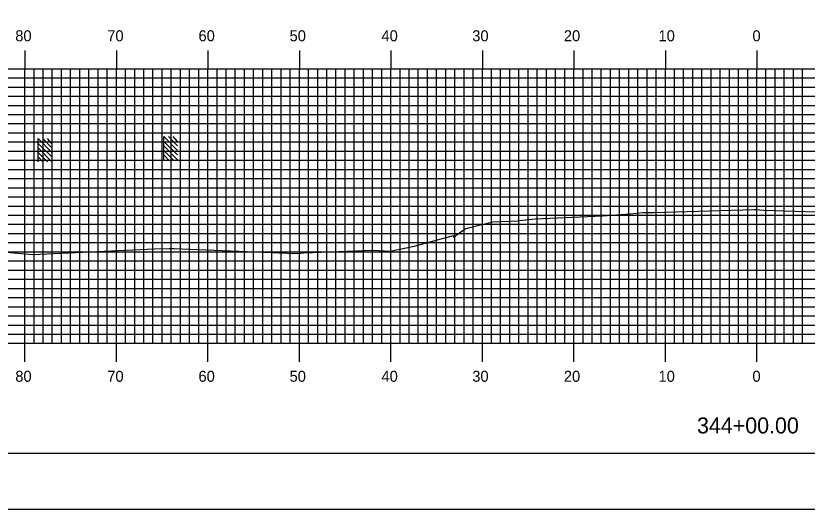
# Model space of a CAD drawing. Extents: x 1825540 to 1825883, y 442591 to 442811.
# Drawn here: x 1825624.9 to 1825711.4, y 442590.5 to 442644.4 of the extents above; entities that cross this region are included whole.
import ezdxf

# ---------------------------------------------------------------- set-up
doc = ezdxf.new("R2010")
doc.units = 0
for name, color, linetype in [('BORDER', 7, 'Continuous'), ('H_V ANNOTATION', 7, 'Continuous'), ('M_Buildings_Rooftop', 7, 'Continuous'), ('MAJOR', 7, 'Continuous'), ('MINOR', 7, 'Continuous'), ('PLOT BOUNDARY', 7, 'Continuous'), ('S_Roadway_Centerline', 7, 'Continuous')]:
    doc.layers.add(name, color=color, linetype=linetype)

msp = doc.modelspace()

# ---------------------------------------------------------------- linework, layer by layer
at = {"layer": 'BORDER'}
msp.add_lwpolyline([(1825556.274, 442596.665), (1825876.274, 442596.665), (1825876.274, 442806.665), (1825556.274, 442806.665)], close=True, dxfattribs=at)
at = {"layer": 'M_Buildings_Rooftop'}
for p, q in [((1825641.046, 442628.725), (1825641.046, 442631.251)), ((1825642.555, 442629.742), (1825641.046, 442631.251)), ((1825642.555, 442630.234), (1825641.571, 442631.251)), ((1825642.555, 442630.726), (1825642.063, 442631.251)), ((1825627.311, 442628.501), (1825627.311, 442631.027)), ((1825628.821, 442629.518), (1825627.311, 442631.027)), ((1825628.821, 442629.026), (1825627.311, 442630.502)), ((1825628.821, 442630.01), (1825627.836, 442631.027)), ((1825628.821, 442630.502), (1825628.328, 442631.027)), ((1825642.555, 442629.25), (1825641.046, 442630.726)), ((1825642.555, 442628.725), (1825641.046, 442630.234)), ((1825628.821, 442628.501), (1825627.311, 442630.01)), ((1825628.328, 442628.501), (1825627.311, 442629.518)), ((1825642.063, 442628.725), (1825641.046, 442629.742)), ((1825627.836, 442628.501), (1825627.311, 442629.026)), ((1825641.571, 442628.725), (1825641.046, 442629.25))]:
    msp.add_line(p, q, dxfattribs=at)
at = {"layer": 'MAJOR'}
for p, q in [((1825625.874, 442640.669), (1825625.874, 442638.665)), ((1825635.874, 442640.669), (1825635.874, 442638.665)), ((1825645.874, 442640.669), (1825645.874, 442638.665)), ((1825655.874, 442640.669), (1825655.874, 442638.665)), ((1825665.874, 442640.669), (1825665.874, 442638.665)), ((1825675.874, 442640.669), (1825675.874, 442638.665)), ((1825685.874, 442640.669), (1825685.874, 442638.665)), ((1825695.874, 442640.669), (1825695.874, 442638.665)), ((1825705.874, 442640.669), (1825705.874, 442638.665)), ((1825565.874, 442638.665), (1825845.874, 442638.665)), ((1825565.874, 442638.665), (1825845.874, 442638.665)), ((1825625.874, 442608.665), (1825625.874, 442638.665)), ((1825635.874, 442608.665), (1825635.874, 442638.665)), ((1825645.874, 442608.665), (1825645.874, 442638.665)), ((1825655.874, 442608.665), (1825655.874, 442638.665)), ((1825665.874, 442608.665), (1825665.874, 442638.665)), ((1825675.874, 442608.665), (1825675.874, 442638.665)), ((1825685.874, 442608.665), (1825685.874, 442638.665)), ((1825695.874, 442608.665), (1825695.874, 442638.665)), ((1825705.874, 442608.665), (1825705.874, 442638.665)), ((1825565.874, 442633.665), (1825845.874, 442633.665)), ((1825565.874, 442628.665), (1825845.874, 442628.665)), ((1825565.874, 442623.665), (1825845.874, 442623.665)), ((1825565.874, 442618.665), (1825845.874, 442618.665)), ((1825565.874, 442613.665), (1825845.874, 442613.665)), ((1825565.874, 442608.665), (1825845.874, 442608.665)), ((1825565.874, 442608.665), (1825845.874, 442608.665)), ((1825625.874, 442606.661), (1825625.874, 442608.665)), ((1825635.874, 442606.661), (1825635.874, 442608.665)), ((1825645.874, 442606.661), (1825645.874, 442608.665)), ((1825655.874, 442606.661), (1825655.874, 442608.665)), ((1825665.874, 442606.661), (1825665.874, 442608.665)), ((1825675.874, 442606.661), (1825675.874, 442608.665)), ((1825685.874, 442606.661), (1825685.874, 442608.665)), ((1825695.874, 442606.661), (1825695.874, 442608.665)), ((1825705.874, 442606.661), (1825705.874, 442608.665))]:
    msp.add_line(p, q, dxfattribs=at)
at = {"layer": 'MINOR'}
for p, q in [((1825626.874, 442608.665), (1825626.874, 442638.665)), ((1825627.874, 442608.665), (1825627.874, 442638.665)), ((1825628.874, 442608.665), (1825628.874, 442638.665)), ((1825629.874, 442608.665), (1825629.874, 442638.665)), ((1825630.874, 442608.665), (1825630.874, 442638.665)), ((1825631.874, 442608.665), (1825631.874, 442638.665)), ((1825632.874, 442608.665), (1825632.874, 442638.665)), ((1825633.874, 442608.665), (1825633.874, 442638.665)), ((1825634.874, 442608.665), (1825634.874, 442638.665)), ((1825636.874, 442608.665), (1825636.874, 442638.665)), ((1825637.874, 442608.665), (1825637.874, 442638.665)), ((1825638.874, 442608.665), (1825638.874, 442638.665)), ((1825639.874, 442608.665), (1825639.874, 442638.665)), ((1825640.874, 442608.665), (1825640.874, 442638.665)), ((1825641.874, 442608.665), (1825641.874, 442638.665)), ((1825642.874, 442608.665), (1825642.874, 442638.665)), ((1825643.874, 442608.665), (1825643.874, 442638.665)), ((1825644.874, 442608.665), (1825644.874, 442638.665)), ((1825646.874, 442608.665), (1825646.874, 442638.665)), ((1825647.874, 442608.665), (1825647.874, 442638.665)), ((1825648.874, 442608.665), (1825648.874, 442638.665)), ((1825649.874, 442608.665), (1825649.874, 442638.665)), ((1825650.874, 442608.665), (1825650.874, 442638.665)), ((1825651.874, 442608.665), (1825651.874, 442638.665)), ((1825652.874, 442608.665), (1825652.874, 442638.665)), ((1825653.874, 442608.665), (1825653.874, 442638.665)), ((1825654.874, 442608.665), (1825654.874, 442638.665)), ((1825656.874, 442608.665), (1825656.874, 442638.665)), ((1825657.874, 442608.665), (1825657.874, 442638.665)), ((1825658.874, 442608.665), (1825658.874, 442638.665)), ((1825659.874, 442608.665), (1825659.874, 442638.665)), ((1825660.874, 442608.665), (1825660.874, 442638.665)), ((1825661.874, 442608.665), (1825661.874, 442638.665)), ((1825662.874, 442608.665), (1825662.874, 442638.665)), ((1825663.874, 442608.665), (1825663.874, 442638.665)), ((1825664.874, 442608.665), (1825664.874, 442638.665)), ((1825666.874, 442608.665), (1825666.874, 442638.665)), ((1825667.874, 442608.665), (1825667.874, 442638.665)), ((1825668.874, 442608.665), (1825668.874, 442638.665)), ((1825669.874, 442608.665), (1825669.874, 442638.665)), ((1825670.874, 442608.665), (1825670.874, 442638.665)), ((1825671.874, 442608.665), (1825671.874, 442638.665)), ((1825672.874, 442608.665), (1825672.874, 442638.665)), ((1825673.874, 442608.665), (1825673.874, 442638.665)), ((1825674.874, 442608.665), (1825674.874, 442638.665)), ((1825676.874, 442608.665), (1825676.874, 442638.665)), ((1825677.874, 442608.665), (1825677.874, 442638.665)), ((1825678.874, 442608.665), (1825678.874, 442638.665)), ((1825679.874, 442608.665), (1825679.874, 442638.665)), ((1825680.874, 442608.665), (1825680.874, 442638.665)), ((1825681.874, 442608.665), (1825681.874, 442638.665)), ((1825682.874, 442608.665), (1825682.874, 442638.665)), ((1825683.874, 442608.665), (1825683.874, 442638.665)), ((1825684.874, 442608.665), (1825684.874, 442638.665)), ((1825686.874, 442608.665), (1825686.874, 442638.665)), ((1825687.874, 442608.665), (1825687.874, 442638.665)), ((1825688.874, 442608.665), (1825688.874, 442638.665)), ((1825689.874, 442608.665), (1825689.874, 442638.665)), ((1825690.874, 442608.665), (1825690.874, 442638.665)), ((1825691.874, 442608.665), (1825691.874, 442638.665)), ((1825692.874, 442608.665), (1825692.874, 442638.665)), ((1825693.874, 442608.665), (1825693.874, 442638.665)), ((1825694.874, 442608.665), (1825694.874, 442638.665)), ((1825696.874, 442608.665), (1825696.874, 442638.665)), ((1825697.874, 442608.665), (1825697.874, 442638.665)), ((1825698.874, 442608.665), (1825698.874, 442638.665)), ((1825699.874, 442608.665), (1825699.874, 442638.665)), ((1825700.874, 442608.665), (1825700.874, 442638.665)), ((1825701.874, 442608.665), (1825701.874, 442638.665)), ((1825702.874, 442608.665), (1825702.874, 442638.665)), ((1825703.874, 442608.665), (1825703.874, 442638.665)), ((1825704.874, 442608.665), (1825704.874, 442638.665)), ((1825706.874, 442608.665), (1825706.874, 442638.665)), ((1825707.874, 442608.665), (1825707.874, 442638.665)), ((1825708.874, 442608.665), (1825708.874, 442638.665)), ((1825709.874, 442608.665), (1825709.874, 442638.665)), ((1825710.874, 442608.665), (1825710.874, 442638.665)), ((1825565.874, 442637.665), (1825845.874, 442637.665)), ((1825565.874, 442636.665), (1825845.874, 442636.665)), ((1825565.874, 442635.665), (1825845.874, 442635.665)), ((1825565.874, 442634.665), (1825845.874, 442634.665)), ((1825565.874, 442632.665), (1825845.874, 442632.665)), ((1825565.874, 442631.665), (1825845.874, 442631.665)), ((1825565.874, 442630.665), (1825845.874, 442630.665)), ((1825565.874, 442629.665), (1825845.874, 442629.665)), ((1825565.874, 442627.665), (1825845.874, 442627.665)), ((1825565.874, 442626.665), (1825845.874, 442626.665)), ((1825565.874, 442625.665), (1825845.874, 442625.665)), ((1825565.874, 442624.665), (1825845.874, 442624.665)), ((1825565.874, 442622.665), (1825845.874, 442622.665)), ((1825565.874, 442621.665), (1825845.874, 442621.665)), ((1825565.874, 442620.665), (1825845.874, 442620.665)), ((1825565.874, 442619.665), (1825845.874, 442619.665)), ((1825565.874, 442617.665), (1825845.874, 442617.665)), ((1825565.874, 442616.665), (1825845.874, 442616.665)), ((1825565.874, 442615.665), (1825845.874, 442615.665)), ((1825565.874, 442614.665), (1825845.874, 442614.665)), ((1825565.874, 442612.665), (1825845.874, 442612.665)), ((1825565.874, 442611.665), (1825845.874, 442611.665)), ((1825565.874, 442610.665), (1825845.874, 442610.665)), ((1825565.874, 442609.665), (1825845.874, 442609.665))]:
    msp.add_line(p, q, dxfattribs=at)
at = {"layer": 'PLOT BOUNDARY'}
msp.add_lwpolyline([(1825540.087, 442590.547), (1825880.087, 442590.547), (1825880.087, 442810.547), (1825540.087, 442810.547)], close=True, dxfattribs=at)
msp.add_lwpolyline([(1825540.087, 442590.547), (1825880.087, 442590.547), (1825880.087, 442810.547), (1825540.087, 442810.547)], close=True, dxfattribs=at)
at = {"layer": 'S_Roadway_Centerline'}
msp.add_lwpolyline([(1825623.466, 442618.674), (1825626.704, 442618.365), (1825640.056, 442619), (1825641.631, 442619.01), (1825642.204, 442619.024), (1825654.542, 442618.508), (1825655.699, 442618.471), (1825656.377, 442618.565), (1825663.952, 442618.852), (1825665.806, 442618.721), (1825668.429, 442619.265), (1825672.724, 442620.458), (1825672.732, 442620.279), (1825674.011, 442621.158), (1825674.347, 442621.298), (1825677.018, 442621.94), (1825679.748, 442622.054), (1825679.92, 442622.085), (1825681.636, 442622.248), (1825689.021, 442622.606), (1825692.025, 442622.803), (1825693.412, 442622.952), (1825694.598, 442622.965), (1825705.54, 442623.271), (1825705.774, 442623.292), (1825706.637, 442623.226), (1825715.7, 442622.926)], dxfattribs=at)

# ---------------------------------------------------------------- texts
at = {"layer": 'H_V ANNOTATION'}
for s, height, p in [('80', 1.2, (1825624.825, 442641.665)), ('70', 1.2, (1825634.878, 442641.665)), ('60', 1.2, (1825644.846, 442641.665)), ('50', 1.2, (1825654.803, 442641.665)), ('40', 1.2, (1825664.846, 442641.665)), ('30', 1.2, (1825674.771, 442641.665)), ('20', 1.2, (1825684.782, 442641.665)), ('10', 1.2, (1825695.125, 442641.665)), ('0', 1.2, (1825705.392, 442641.665)), ('80', 1.2, (1825624.825, 442604.465)), ('70', 1.2, (1825634.878, 442604.465)), ('60', 1.2, (1825644.846, 442604.465)), ('50', 1.2, (1825654.803, 442604.465)), ('40', 1.2, (1825664.846, 442604.465)), ('30', 1.2, (1825674.771, 442604.465)), ('20', 1.2, (1825684.782, 442604.465)), ('10', 1.2, (1825695.125, 442604.465)), ('0', 1.2, (1825705.392, 442604.465)), ('344+00.00', 1.75, (1825699.335, 442598.821))]:
    msp.add_text(s, height=height, dxfattribs=at).set_placement(p)
at = {"layer": 'S_Roadway_Centerline'}
for s, p in [('L', (1825705.766, 442623.284)), ('C', (1825705.769, 442623.292))]:
    msp.add_text(s, height=0.0146, dxfattribs=at).set_placement(p)

doc.saveas('drawing.dxf')
